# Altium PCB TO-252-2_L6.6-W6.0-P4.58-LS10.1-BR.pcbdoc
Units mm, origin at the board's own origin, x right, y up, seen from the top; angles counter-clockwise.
Board outline 23.71 x 19.39 mm, 2 copper layers (Top Layer, Bottom Layer), stack 0 mm thick; 1 components, 0 nets, 3 pads, 0 vias.
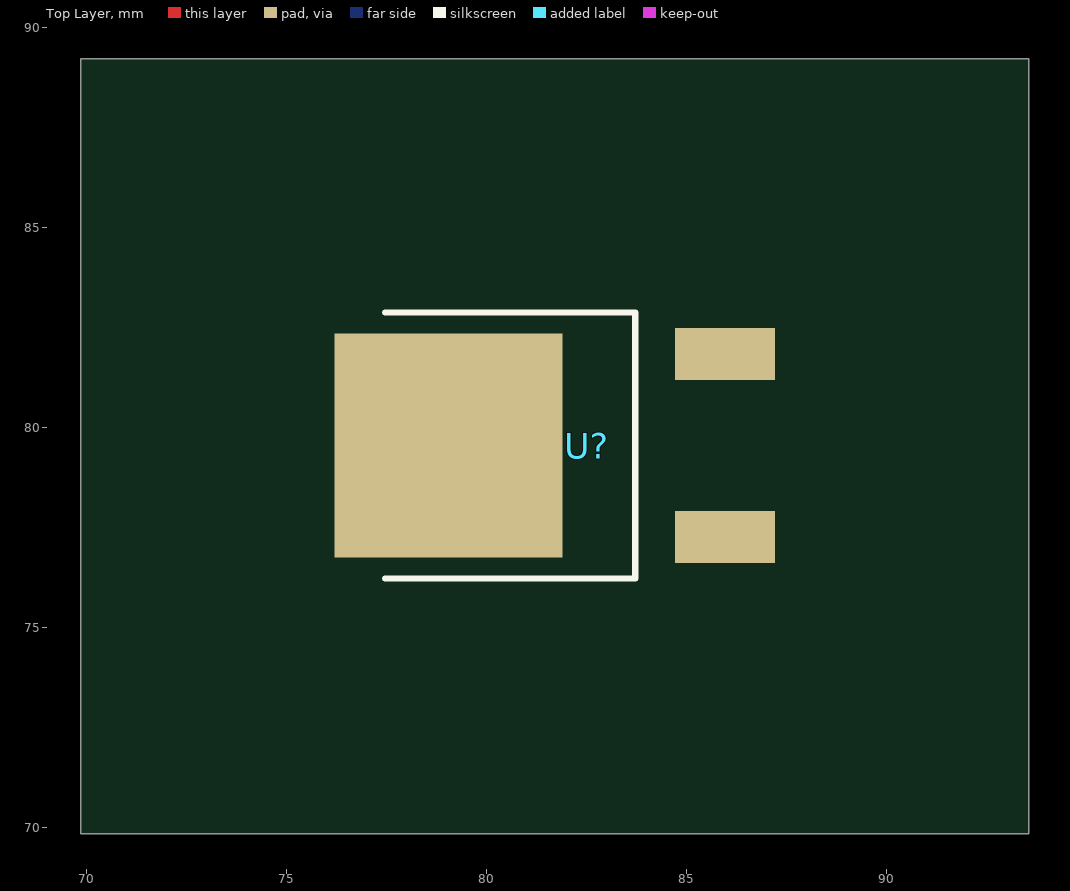
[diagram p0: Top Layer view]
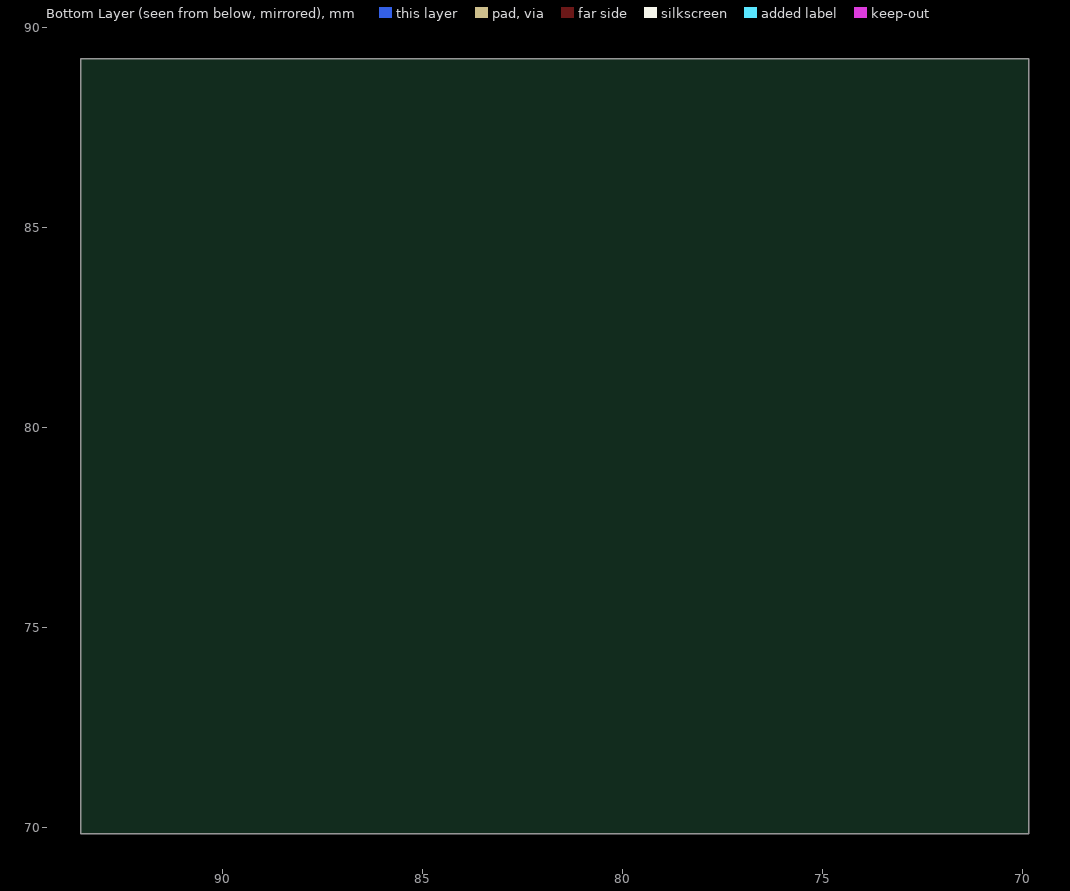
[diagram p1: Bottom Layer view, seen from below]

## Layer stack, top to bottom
Top Layer: signal copper (thickness not stored)
Bottom Layer: signal copper (thickness not stored)

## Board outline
93.56,69.85 69.85,69.85 69.85,89.236 93.56,89.236

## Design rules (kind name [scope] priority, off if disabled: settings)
PasteMaskExpansion "Paste Mask Expansion" [All] p1: expansion=0
SolderMaskExpansion "Solder Mask Expansion" [IsVia] p1: expansion=-25.4 istentingtop=TRUE
SolderMaskExpansion "Solder Mask Expansion" [All] p2: expansion=0.051 istentingtop=FALSE

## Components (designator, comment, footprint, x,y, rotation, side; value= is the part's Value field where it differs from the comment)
U? "" TO-252-2_L6.6-W6.0-P4.58-LS10.1-BR 82.505,79.56 r0 top

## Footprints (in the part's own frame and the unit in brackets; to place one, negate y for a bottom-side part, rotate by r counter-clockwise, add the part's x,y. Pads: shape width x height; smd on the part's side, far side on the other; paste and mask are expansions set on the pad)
TO-252-2_L6.6-W6.0-P4.58-LS10.1-BR [mm]
  rect 2.5x1.3 smd: 1(3.455,-2.29) 3(3.455,2.29)
  rect 5.7x5.6 smd: 2(-3.455,0)
  silkscreen extent -5.04,-3.33 1.21,3.33

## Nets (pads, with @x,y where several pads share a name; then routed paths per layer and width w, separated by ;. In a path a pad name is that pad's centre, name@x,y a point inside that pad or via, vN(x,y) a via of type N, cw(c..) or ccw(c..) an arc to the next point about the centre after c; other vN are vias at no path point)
pads on no net: U?.1 U?.2 U?.3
